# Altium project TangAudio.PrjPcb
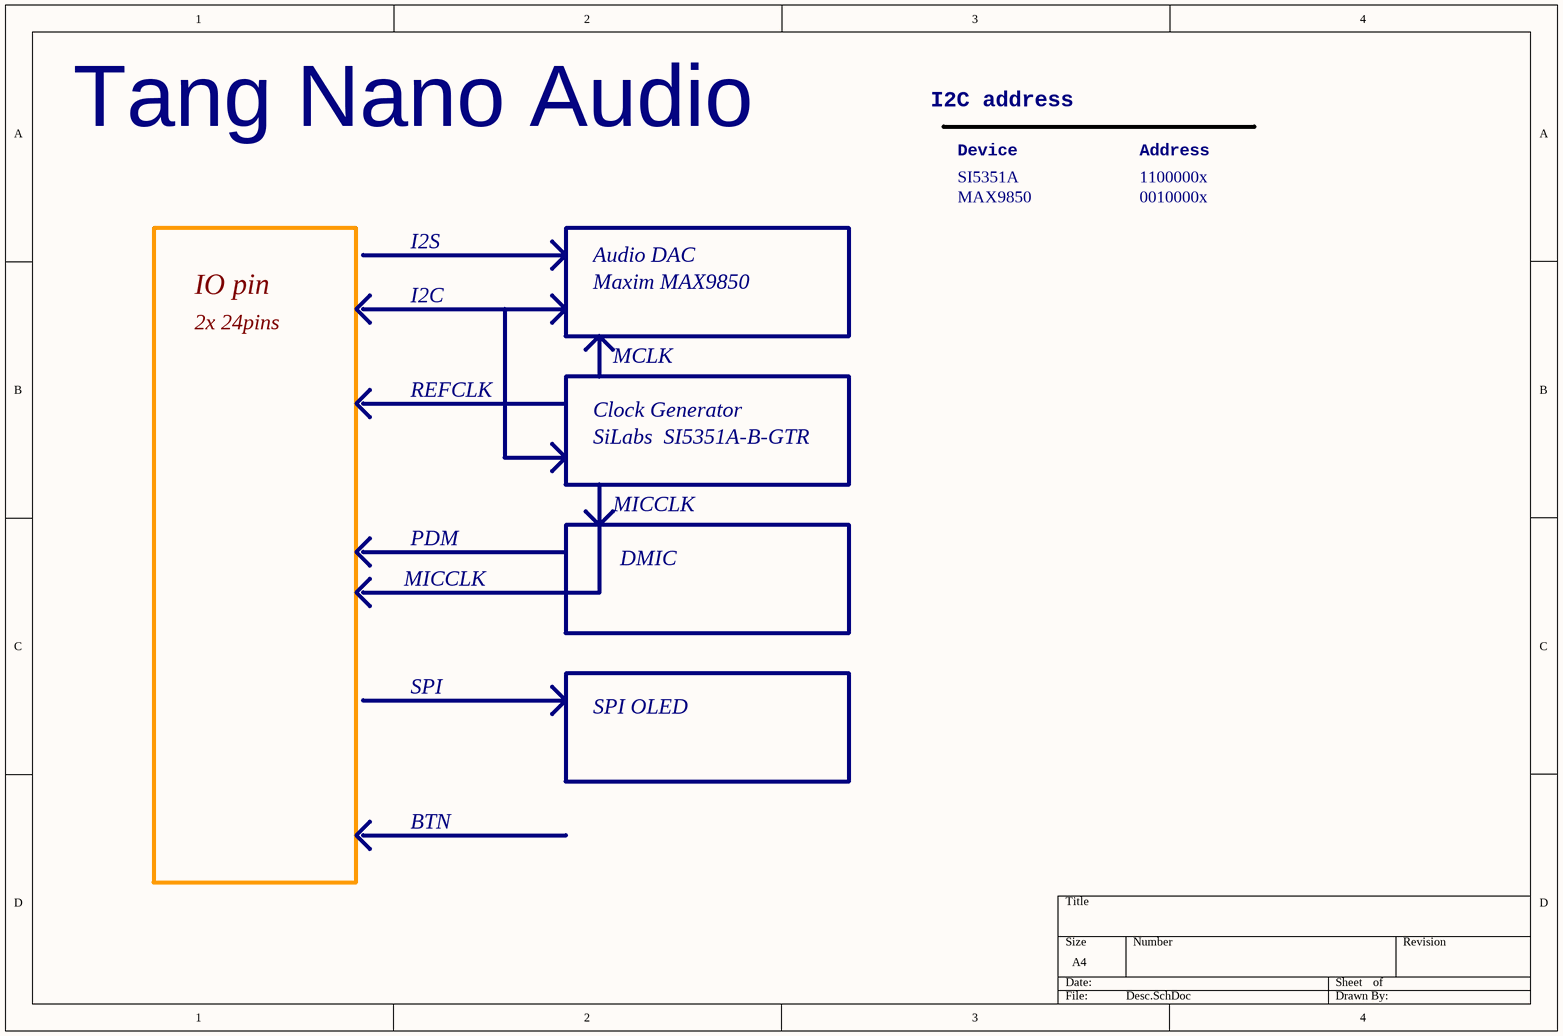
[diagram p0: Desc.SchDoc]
5 sheets, 68 parts. Net scope: global (net labels, ports and power ports of the same name join across sheets).
Board file: PCB.PcbDoc
Sheets:
  Desc.SchDoc
  AUX.SchDoc
  IO.SchDoc
  DAC.SchDoc
  License.SchDoc

## Sheet Desc.SchDoc
size A4; SheetNumber: 1; SheetTotal: 4

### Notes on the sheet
- I2C address
- Tang Nano Audio
- Device
- Address
- I2S
- SI5351A
- MAX9850
- 1100000x
- 0010000x
- IO pin
- I2C
- Audio DAC
- Maxim MAX9850
- 2x 24pins
- MCLK
- REFCLK
- Clock Generator
- SiLabs  SI5351A-B-GTR
- MICCLK
- PDM
- DMIC
- SPI
- SPI OLED
- BTN

## Sheet AUX.SchDoc
size A4; SheetNumber: 2; SheetTotal: 4
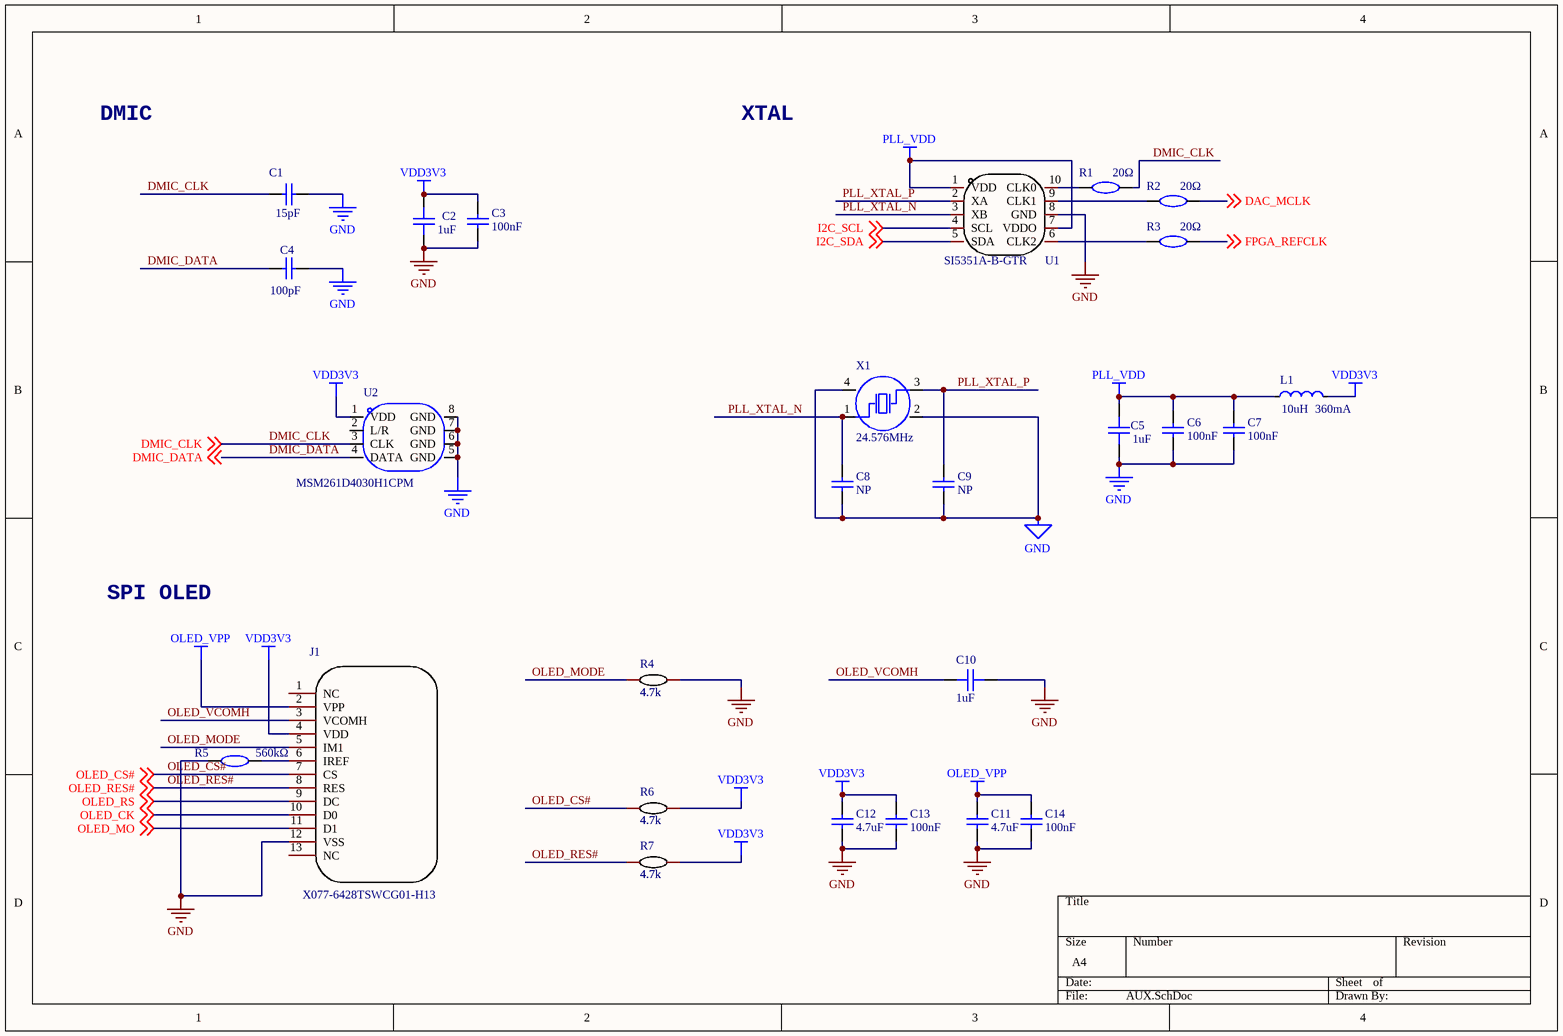
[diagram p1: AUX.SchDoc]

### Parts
C1  value 15pF  [C0402]
C2  value 1uF  [C0603]
C3  value 100nF  [C0402]
C4  value 100pF  [C0402]
C5  value 1uF  [C0603]
C6  value 100nF  [C0402]
C7  value 100nF  [C0402]
C8  value NP  [C0402]
C9  value NP  [C0402]
C10  value 1uF  [C0603]
C11  value 4.7uF  [C0603]
C12  value 4.7uF  [C0603]
C13  value 100nF  [C0402]
C14  value 100nF  [C0402]
J1  X077-6428TSWCG01-H13  [OLED]
L1  value 10uH  Rated Current: 360mA  [L0805]
R1  value 20Ω  [R0402]
R2  value 20Ω  [R0402]
R3  value 20Ω  [R0402]
R4  4.7k  [R0402]
R5  value 560kΩ  [R0402]
R6  4.7k  [R0402]
R7  4.7k  [R0402]
U1  SI5351A-B-GTR  [MSOP-10_L3.0-W3.0-P0.50-LS5.0-BL]
U2  (no value)  [MIC-SMD_8P-L3.0-W4.0-P0.85-BL]
X1  value 24.576MHz  [OSC-SMD_4P-L3.2-W2.5-BL]

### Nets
GND: C1.2 C2.1 C3.1 C4.2 C5.1 C6.1 C7.1 C8.2 C9.2 C10.1 C11.2 C12.2 C13.1 C14.1 J1.12(VSS) R4.2 R5.1 U1.8(GND) U2.5(GND) U2.6(GND) U2.7(GND) U2.8(GND) X1.2(GND) X1.4(GND)
OLED_VPP: C11.1 C14.2 J1.2(VPP)
PLL_VDD: C5.2 C6.2 C7.2 L1.1 U1.1(VDD) U1.7(VDDO)
VDD3V3: C2.2 C3.2 C12.1 C13.2 J1.4(VDD) L1.2 R6.2 R7.2 U2.1(VDD)
DAC_MCLK: R2.2 ; off-sheet DAC_MCLK
DMIC_CLK: C1.1 R1.2 U2.3(CLK) ; off-sheet DMIC_CLK
DMIC_DATA: C4.1 U2.4(DATA) ; off-sheet DMIC_DATA
FPGA_REFCLK: R3.2 ; off-sheet FPGA_REFCLK
I2C_SCL: U1.4(SCL) ; off-sheet I2C_SCL
I2C_SDA: U1.5(SDA) ; off-sheet I2C_SDA
OLED_CK: J1.10(D0) ; off-sheet OLED_CK
OLED_CS#: J1.7(CS) R6.1 ; off-sheet OLED_CS#
OLED_MO: J1.11(D1) ; off-sheet OLED_MO
OLED_MODE: J1.5(IM1) R4.1
OLED_RES#: J1.8(RES) R7.1 ; off-sheet OLED_RES#
OLED_RS: J1.9(DC) ; off-sheet OLED_RS
OLED_VCOMH: C10.2 J1.3(VCOMH)
PLL_XTAL_N: C8.1 U1.3(XB) X1.1(OSC1)
PLL_XTAL_P: C9.1 U1.2(XA) X1.3(OSC2)
NetJ1_6: J1.6(IREF) R5.2
NetR1_1: R1.1 U1.10(CLK0)
NetR2_1: R2.1 U1.9(CLK1)
NetR3_1: R3.1 U1.6(CLK2)

Not connected (* = marked no-connect by the designer): J1 1(NC) 13(NC); U2 2(L/R)

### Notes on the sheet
- DMIC
- XTAL
- SPI OLED

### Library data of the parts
C1 C8 C9 = 0402CG150J500NT: Manufacturer: FH(风华); Add into BOM: yes; Tolerance: ±5%; Voltage Rated: 50V; Temperature Coefficient: C0G
C2 C5 C10 = CL05A105KA5NQNC: Manufacturer: SAMSUNG(三星); Add into BOM: yes; Tolerance: ±10%; Voltage Rated: 25V; Temperature Coefficient: X5R
C3 C6 C7 C13 C14 = CL05B104KO5NNNC: Manufacturer: SAMSUNG(三星); Add into BOM: yes; Tolerance: ±10%; Voltage Rated: 16V; Temperature Coefficient: X7R
C4 = 0402CG101J500NT: Manufacturer: FH(风华); Add into BOM: yes; Tolerance: ±5%; Voltage Rated: 50V; Temperature Coefficient: C0G
C11 C12 = CL10A475KO8NNNC: Manufacturer: SAMSUNG(三星); Add into BOM: yes; Tolerance: ±10%; Voltage Rated: 16V; Temperature Coefficient: X5R
L1 = SLM2012100MIT: Manufacturer: Sunltech(韩国顺磁); Add into BOM: yes; Tolerance: ±20%; DC Resistance (DCR): 550mΩ
R1-R3 R5 = 0603WAF200JT5E: Manufacturer: UNI-ROYAL(厚声); Add into BOM: yes; Tolerance: ±1%; Power(Watts): 1/10W; Temperature Coefficient: ±100ppm/; Overload Voltage (Max): 75V
R4 R6 R7 = Res_0603: Symbol: 电阻; Convert to PCB: yes
U1 = SI5351A-B-GTR: Manufacturer: SILICON LABS(芯科); Add into BOM: yes
U2 = MSM261D4030H1CPM: Manufacturer: MEMS(敏芯微); Add into BOM: yes
X1 = X322525MOB4SI: Manufacturer: YXC扬兴科技; Add into BOM: yes; Crystal Type: 贴片无源晶振; Frequency Tolerance: ±10ppm; Frequency Stability: ±30ppm; Load Capacitance: 12pF

## Sheet IO.SchDoc
size B; SheetNumber: 3; SheetTotal: 4
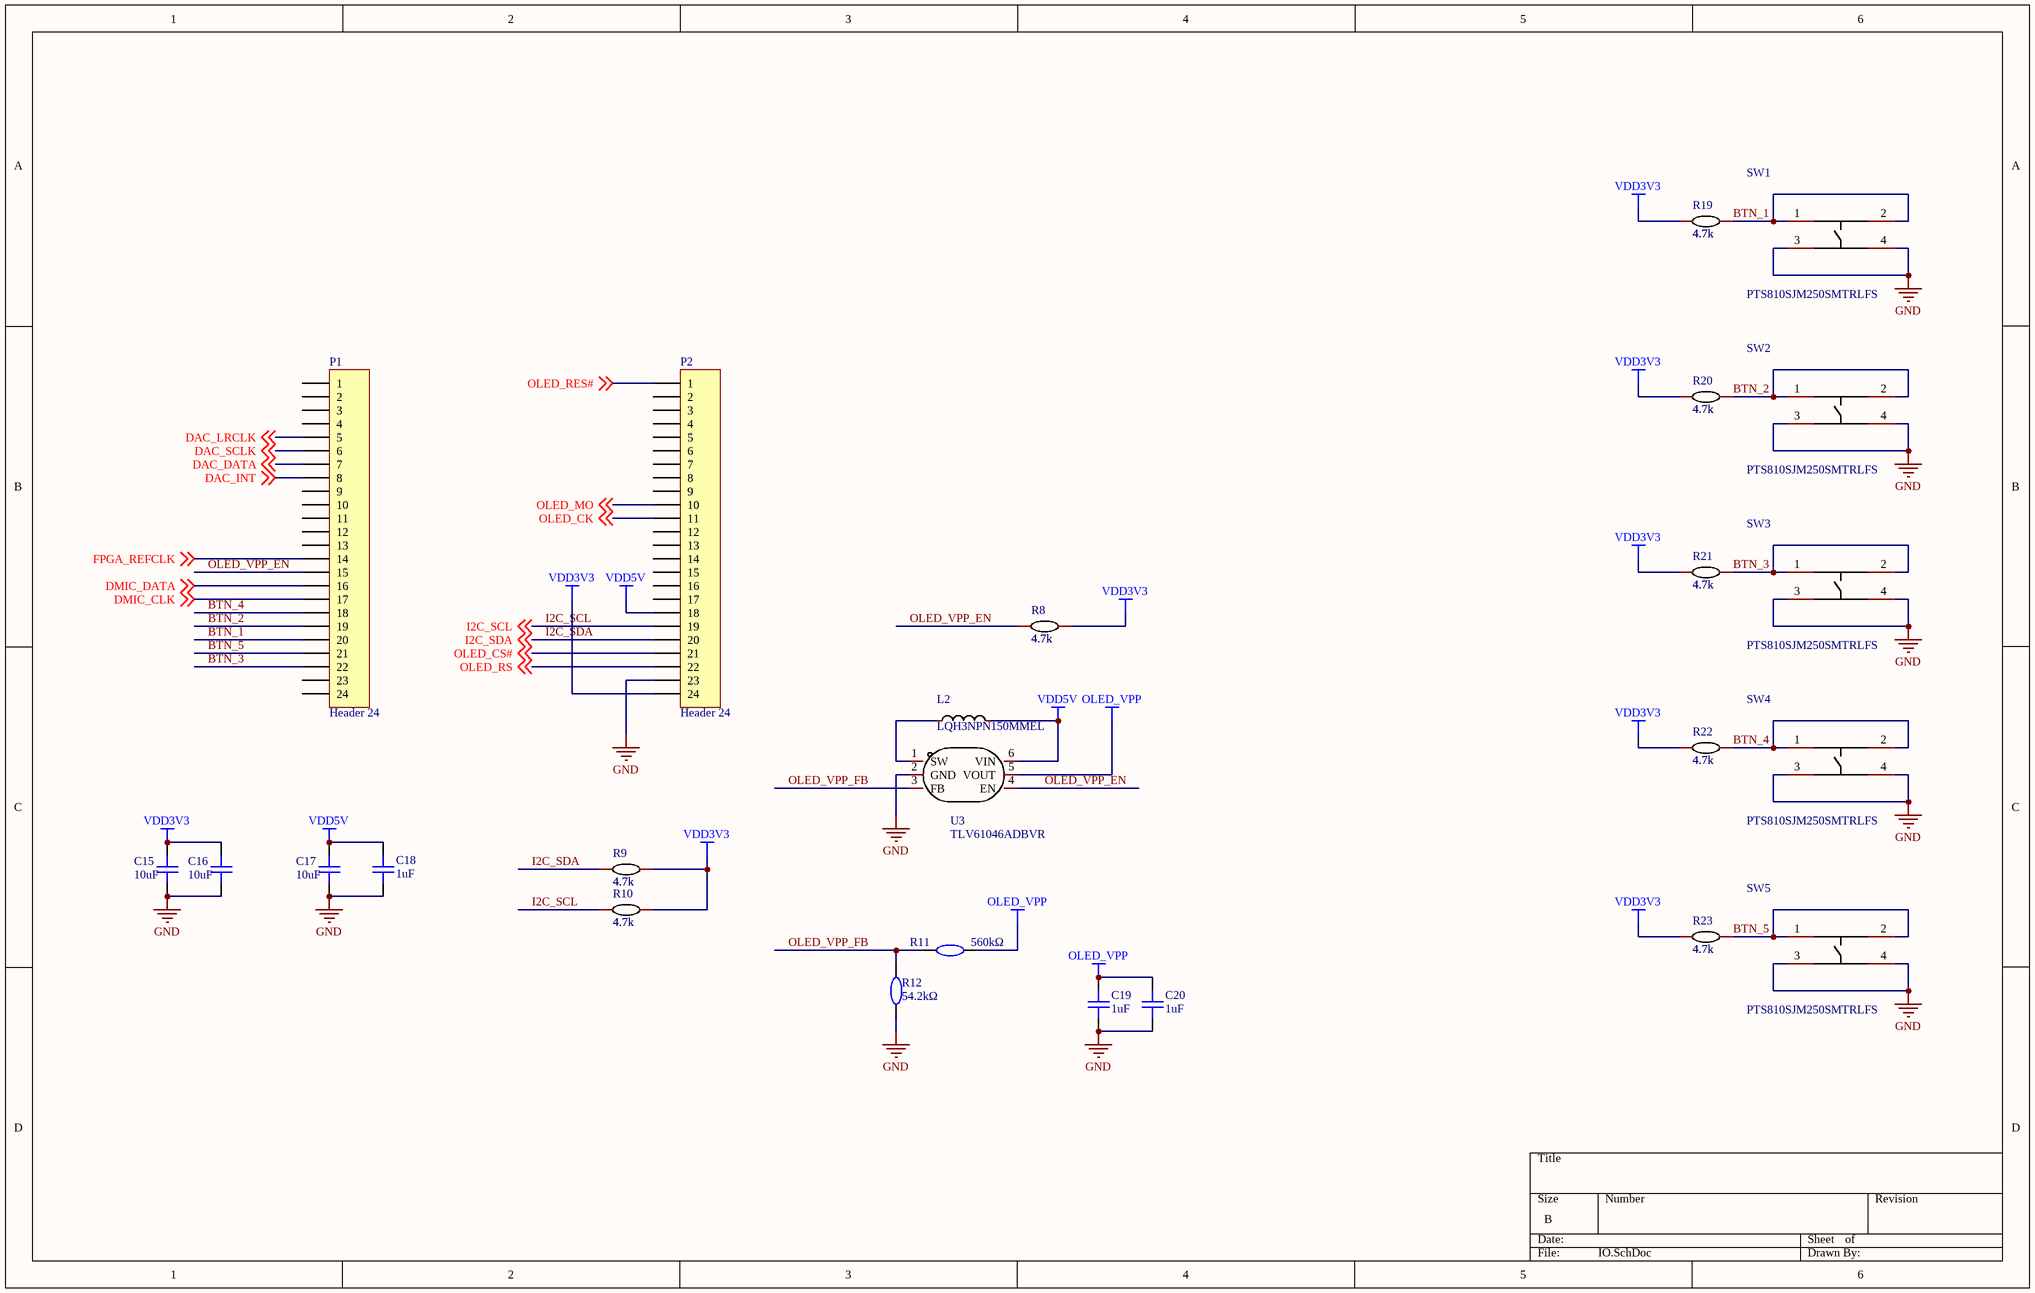
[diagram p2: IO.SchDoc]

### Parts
C15  value 10uF  [C0603]
C16  value 10uF  [C0603]
C17  value 10uF  [C0603]
C18  value 1uF  [C0603]
C19  value 1uF  [C0603]
C20  value 1uF  [C0603]
L2  LQH3NPN150MMEL  [IND-SMD_L3.0-W3.0_LQH3NPN]
P1  Header 24  [HDR1X24]
P2  Header 24  [HDR1X24]
R8  4.7k  [R0402]
R9  4.7k  [R0402]
R10  4.7k  [R0402]
R11  value 560kΩ  [R0402]
R12  value 54.2kΩ  [R0402]
R19  4.7k  [R0402]
R20  4.7k  [R0402]
R21  4.7k  [R0402]
R22  4.7k  [R0402]
R23  4.7k  [R0402]
SW1  PTS810SJM250SMTRLFS  [KEY-SMD_4P-L4.2-W3.2-P2.20-LS4.6]
SW2  PTS810SJM250SMTRLFS  [KEY-SMD_4P-L4.2-W3.2-P2.20-LS4.6]
SW3  PTS810SJM250SMTRLFS  [KEY-SMD_4P-L4.2-W3.2-P2.20-LS4.6]
SW4  PTS810SJM250SMTRLFS  [KEY-SMD_4P-L4.2-W3.2-P2.20-LS4.6]
SW5  PTS810SJM250SMTRLFS  [KEY-SMD_4P-L4.2-W3.2-P2.20-LS4.6]
U3  TLV61046ADBVR  [SOT-23-6_L2.9-W1.6-P0.95-LS2.8-BL]

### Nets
GND: C15.2 C16.2 C17.2 C18.2 C19.2 C20.2 P2.23 R12.1 SW1.3 SW1.4 SW2.3 SW2.4 SW3.3 SW3.4 SW4.3 SW4.4 SW5.3 SW5.4 U3.2(GND)
OLED_VPP: C19.1 C20.1 R11.2 U3.5(VOUT)
VDD3V3: C15.1 C16.1 P2.24 R8.2 R9.2 R10.2 R19.1 R20.1 R21.1 R22.1 R23.1
VDD5V: C17.1 C18.1 L2.2 P2.18 U3.6(VIN)
BTN_1: P1.20 R19.2 SW1.1 SW1.2
BTN_2: P1.19 R20.2 SW2.1 SW2.2
BTN_3: P1.22 R21.2 SW3.1 SW3.2
BTN_4: P1.18 R22.2 SW4.1 SW4.2
BTN_5: P1.21 R23.2 SW5.1 SW5.2
DAC_DATA: P1.7 ; off-sheet DAC_DATA
DAC_INT: P1.8 ; off-sheet DAC_INT
DAC_LRCLK: P1.5 ; off-sheet DAC_LRCLK
DAC_SCLK: P1.6 ; off-sheet DAC_SCLK
DMIC_CLK: P1.17 ; off-sheet DMIC_CLK
DMIC_DATA: P1.16 ; off-sheet DMIC_DATA
FPGA_REFCLK: P1.14 ; off-sheet FPGA_REFCLK
I2C_SCL: P2.19 R10.1 ; off-sheet I2C_SCL
I2C_SDA: P2.20 R9.1 ; off-sheet I2C_SDA
OLED_CK: P2.11 ; off-sheet OLED_CK
OLED_CS#: P2.21 ; off-sheet OLED_CS#
OLED_MO: P2.10 ; off-sheet OLED_MO
OLED_RES#: P2.1 ; off-sheet OLED_RES#
OLED_RS: P2.22 ; off-sheet OLED_RS
OLED_VPP_EN: P1.15 R8.1 U3.4(EN)
OLED_VPP_FB: R11.1 R12.2 U3.3(FB)
NetL2_1: L2.1 U3.1(SW)

Not connected (* = marked no-connect by the designer): P1 1 2 3 4 9 10 11 12 13 23 24; P2 2 3 4 5 6 7 8 9 12 13 14 15 16 17

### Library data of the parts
C15-C17 = CL10A106KP8NNNC: Manufacturer: SAMSUNG(三星); Add into BOM: yes; Tolerance: ±10%; Voltage Rated: 10V; Temperature Coefficient: X5R
C18-C20 = CL05A105KA5NQNC: as C2 on sheet AUX
L2 = LQH3NPN150MMEL: Manufacturer: muRata(村田); Name: 15uH; Add into BOM: yes; Value: 15uH; Tolerance: ±20%; Rated Current: 620mA; Saturation Current (Isat): 660mA; DC Resistance (DCR): 290mΩ; Frequency - Self Resonant: 15MHz
P1 P2 = Header 24: Header, 24-Pin
R8-R10 R19-R23 = Res_0603: Symbol: 电阻; Convert to PCB: yes
R11 R12 = 0603WAF200JT5E: as R1 on sheet AUX
SW1-SW5 = PTS810SJM250SMTRLFS: Manufacturer: C&K; Add into BOM: yes; Contact Current: 50mA; Voltage Rating (DC): 16V; Circuit: 单刀单掷; Actuator Style: 圆形按钮; Switch Length: 4.2mm; Switch Width: 3.2mm; Switch Height: 2.5mm
U3 = TLV61046ADBVR: Manufacturer: TI(德州仪器); Add into BOM: yes; Function: 升压型; Output Type: 可调; Number of Outputs: 1; Topology: 升压式; Input Voltage: 1.8V~5.5V; Output Voltage: 3.3V~28V; Switching Frequency: 1.05MHz

## Sheet DAC.SchDoc
size A; SheetNumber: 4; SheetTotal: 4
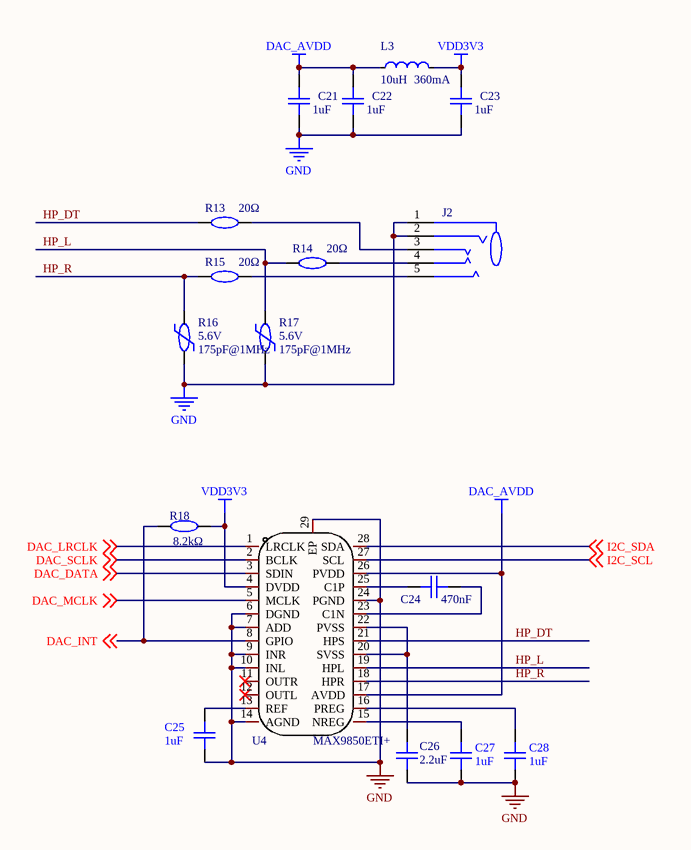
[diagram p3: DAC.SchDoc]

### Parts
C21  value 1uF  [C0603]
C22  value 1uF  [C0603]
C23  value 1uF  [C0603]
C24  value 470nF  [C0603]
C25  value 1uF  [C0603]
C26  value 2.2uF  [C0603]
C27  value 1uF  [C0603]
C28  value 1uF  [C0603]
J2  (no value)  [AUDIO-TH_PJ-3062-HD-G]
L3  value 10uH  Rated Current: 360mA  [L0805]
R13  value 20Ω  [R0402]
R14  value 20Ω  [R0402]
R15  value 20Ω  [R0402]
R16  Allowable Voltage (DC): 5.6V  Typical Capatitance: 175pF@1MHz  [R0402]
R17  Allowable Voltage (DC): 5.6V  Typical Capatitance: 175pF@1MHz  [R0402]
R18  value 8.2kΩ  [R0402]
U4  MAX9850ETI+  [QFN-28_L5.0-W5.0-P0.50-TL-EP3.5]

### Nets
DAC_AVDD: C21.2 C22.2 L3.1 U4.17(AVDD) U4.26(PVDD)
GND: C21.1 C22.1 C23.1 C25.2 C26.1 C27.2 C28.2 J2.1 J2.2 R16.2 R17.2 U4.6(DGND) U4.7(ADD) U4.9(INR) U4.10(INL) U4.14(AGND) U4.24(PGND) U4.29(EP)
VDD3V3: C23.2 L3.2 R18.2 U4.4(DVDD)
DAC_DATA: U4.3(SDIN) ; off-sheet DAC_DATA
DAC_INT: R18.1 U4.8(GPIO) ; off-sheet DAC_INT
DAC_LRCLK: U4.1(LRCLK) ; off-sheet DAC_LRCLK
DAC_MCLK: U4.5(MCLK) ; off-sheet DAC_MCLK
DAC_SCLK: U4.2(BCLK) ; off-sheet DAC_SCLK
HP_DT: R13.1 U4.21(HPS)
HP_L: R14.1 R17.1 U4.19(HPL)
HP_R: R15.1 R16.1 U4.18(HPR)
I2C_SCL: U4.27(SCL) ; off-sheet I2C_SCL
I2C_SDA: U4.28(SDA) ; off-sheet I2C_SDA
NetC24_1: C24.1 U4.25(C1P)
NetC24_2: C24.2 U4.23(C1N)
NetC25_1: C25.1 U4.13(REF)
NetC26_2: C26.2 U4.20(SVSS) U4.22(PVSS)
NetC27_1: C27.1 U4.15(NREG)
NetC28_1: C28.1 U4.16(PREG)
NetJ2_3: J2.3 R13.2
NetJ2_4: J2.4 R14.2
NetJ2_5: J2.5 R15.2

Not connected (* = marked no-connect by the designer): U4 11(OUTR)* 12(OUTL)*

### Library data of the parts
C21-C28 = CL05A105KA5NQNC: as C2 on sheet AUX
J2 = PJ-3062-HD-G: Manufacturer: XKB Connectivity(中国星坤); Add into BOM: yes; Connector Type: 3.5mm耳机座; Current Rating (Max): 500mA; Voltage Rating (Max): 30V; Welding Temperature (Max): 235
L3 = SLM2012100MIT: as L1 on sheet AUX
R13-R15 = 0603WAF200JT5E: as R1 on sheet AUX
R16 R17 = VC040205X150WP: Manufacturer: AVX; Add into BOM: yes; Allowable Voltage (AC): 4V; Clamping Voltage: 18V; Peak Current: 20A; Maximum Energy: 0.05J
R18 = 0402WGF8201TCE: Manufacturer: UNI-ROYAL(厚声); Add into BOM: yes; Tolerance: ±1%; Power(Watts): 1/16W; Temperature Coefficient: ±100ppm/; Overload Voltage (Max): 50V
U4 = MAX9850ETI+: Manufacturer: MAXIM(美信); Add into BOM: yes

## Sheet License.SchDoc
size A4; SheetNumber: 5; SheetTotal: 5
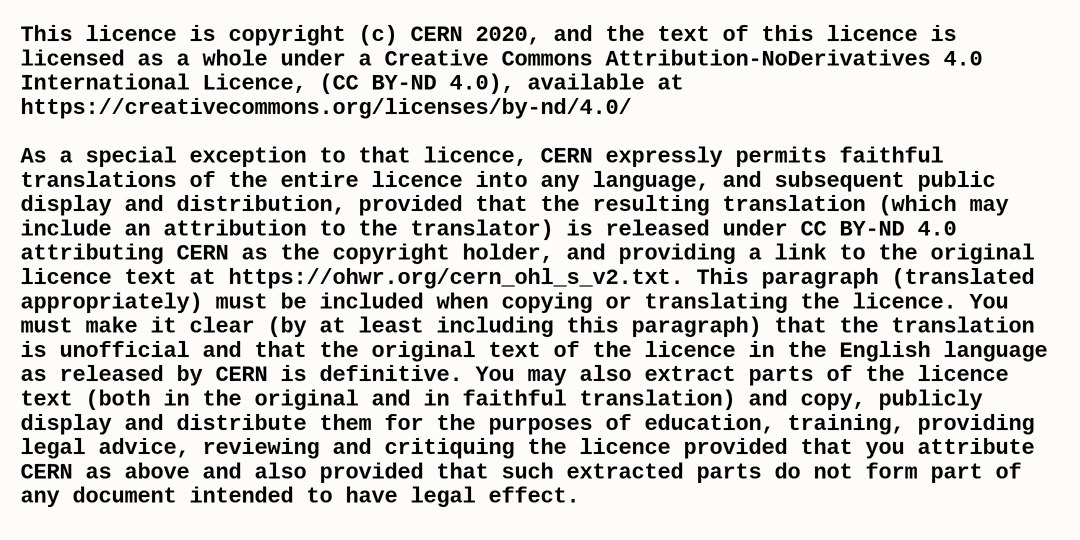
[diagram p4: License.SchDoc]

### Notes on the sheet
- This licence is copyright (c) CERN 2020, and the text of this licence is
  licensed as a whole under a Creative Commons Attribution-NoDerivatives 4.0
  International Licence, (CC BY-ND 4.0), available at
  https://creativecommons.org/licenses/by-nd/4.0/
  As a special exception to that licence, CERN expressly permits faithful
  translations of the entire licence into any language, and subsequent public
  display and distribution, provided that the resulting translation (which may
  include an attribution to the translator) is released under CC BY-ND 4.0
  attributing CERN as the copyright holder, and providing a link to the original
  licence text at https://ohwr.org/cern_ohl_s_v2.txt. This paragraph (translated
  appropriately) must be included when copying or translating the licence. You
  must make it clear (by at least including this paragraph) that the translation
  is unofficial and that the original text of the licence in the English language
  as released by CERN is definitive. You may also extract parts of the licence
  text (both in the original and in faithful translation) and copy, publicly
  display and distribute them for the purposes of education, training, providing
  legal advice, reviewing and critiquing the licence provided that you attribute
  CERN as above and also provided that such extracted parts do not form part of
  any document intended to have legal effect.

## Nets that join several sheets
GND: AUX (24 pins), IO (19 pins), DAC (18 pins)
OLED_VPP: AUX (C11.1 C14.2 J1.2), IO (C19.1 C20.1 R11.2 U3.5)
VDD3V3: AUX (9 pins), IO (11 pins), DAC (C23.2 L3.2 R18.2 U4.4)
DAC_DATA: IO (P1.7), DAC (U4.3)
DAC_INT: IO (P1.8), DAC (R18.1 U4.8)
DAC_LRCLK: IO (P1.5), DAC (U4.1)
DAC_MCLK: AUX (R2.2), DAC (U4.5)
DAC_SCLK: IO (P1.6), DAC (U4.2)
DMIC_CLK: AUX (C1.1 R1.2 U2.3), IO (P1.17)
DMIC_DATA: AUX (C4.1 U2.4), IO (P1.16)
FPGA_REFCLK: AUX (R3.2), IO (P1.14)
I2C_SCL: AUX (U1.4), IO (P2.19 R10.1), DAC (U4.27)
I2C_SDA: AUX (U1.5), IO (P2.20 R9.1), DAC (U4.28)
OLED_CK: AUX (J1.10), IO (P2.11)
OLED_CS#: AUX (J1.7 R6.1), IO (P2.21)
OLED_MO: AUX (J1.11), IO (P2.10)
OLED_RES#: AUX (J1.8 R7.1), IO (P2.1)
OLED_RS: AUX (J1.9), IO (P2.22)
